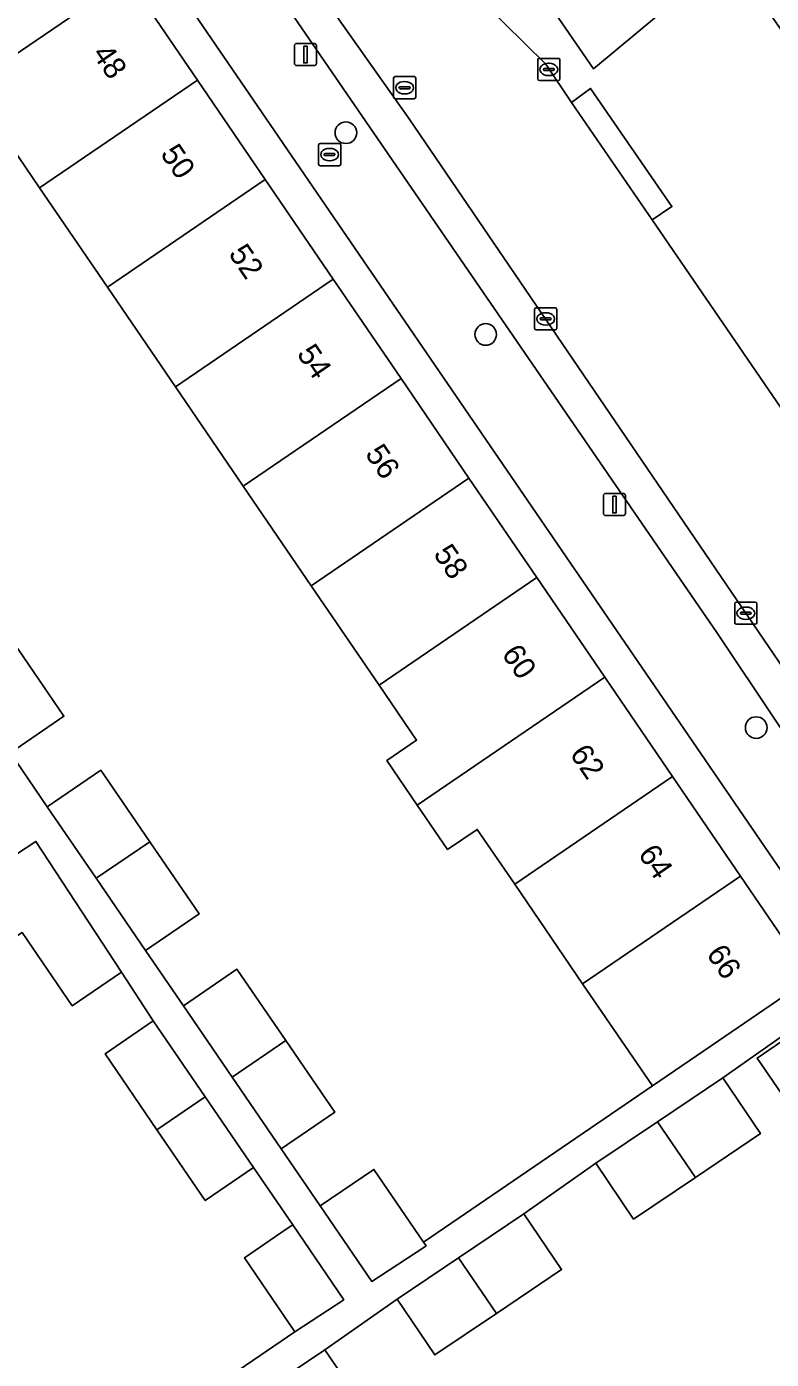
# Model space of a CAD drawing. Extents: x 157445 to 158888, y 383061 to 384688.
# Drawn here: x 158277.7 to 158311.3, y 383793.9 to 383854 of the extents above; entities that cross this region are included whole.
import ezdxf

# ---------------------------------------------------------------- set-up
doc = ezdxf.new("R2010")
doc.units = 0
for name, color, linetype in [('IMGEO_Boom', 7, 'Continuous'), ('IMGEO_Brandkraan', 7, 'Continuous'), ('IMGEO_Erf', 7, 'Continuous'), ('IMGEO_Groenvoorziening', 7, 'Continuous'), ('IMGEO_Kolk', 7, 'Continuous'), ('IMGEO_Lichtmast', 7, 'Continuous'), ('IMGEO_Pand', 7, 'Continuous'), ('IMGEO_Pand_nummerreeks', 7, 'Continuous'), ('IMGEO_Parkeervlak_open', 7, 'Continuous'), ('IMGEO_Rijbaan_lokaal_open', 7, 'Continuous'), ('IMGEO_Rioolput', 7, 'Continuous'), ('IMGEO_Voetpad_open', 7, 'Continuous')]:
    doc.layers.add(name, color=color, linetype=linetype)

msp = doc.modelspace()

# ---------------------------------------------------------------- linework, layer by layer
at = {"layer": 'IMGEO_Boom'}
for centre in [(158292.104, 383849.215), (158298.409, 383840.119), (158310.608, 383822.389)]:
    msp.add_circle(centre, 0.489, dxfattribs=at)
at = {"layer": 'IMGEO_Brandkraan'}
for p, q in [((158290.871, 383847.802), (158290.871, 383848.654)), ((158290.946, 383848.728), (158291.798, 383848.728)), ((158291.872, 383848.654), (158291.872, 383847.802)), ((158291.13, 383848.222), (158291.13, 383848.234)), ((158291.568, 383848.185), (158291.17, 383848.185)), ((158291.173, 383848.271), (158291.571, 383848.271)), ((158291.359, 383848.508), (158291.384, 383848.508)), ((158291.614, 383848.234), (158291.614, 383848.222)), ((158291.798, 383847.728), (158290.946, 383847.728)), ((158291.382, 383847.948), (158291.357, 383847.948))]:
    msp.add_line(p, q, dxfattribs=at)
for points in [[(158290.871, 383847.802), (158290.871, 383848.654)], [(158290.946, 383848.728), (158291.798, 383848.728)], [(158291.872, 383848.654), (158291.872, 383847.802)], [(158291.798, 383847.728), (158290.946, 383847.728)]]:
    msp.add_lwpolyline(points, dxfattribs=at)
for centre, radius, start, end in [((158290.948, 383848.652), 0.0765, 91.55205, 178.44795), ((158290.948, 383848.652), 0.0765, 91.55205, 178.44795), ((158291.796, 383848.652), 0.0765, 1.55205, 88.44795), ((158291.796, 383848.652), 0.0765, 1.55205, 88.44795), ((158291.17, 383848.231), 0.0403, 85.87752, 175.75265), ((158291.167, 383848.221), 0.0366, 178.93798, 274.71019), ((158291.571, 383848.228), 0.043, 264.86636, 352.45326), ((158291.575, 383848.233), 0.0386, 1.73085, 96.63898), ((158290.948, 383847.804), 0.0765, 181.55205, 268.44795), ((158290.948, 383847.804), 0.0765, 181.55205, 268.44795), ((158291.796, 383847.804), 0.0765, 271.55205, 358.44795), ((158291.796, 383847.804), 0.0765, 271.55205, 358.44795)]:
    msp.add_arc(centre, radius, start, end, dxfattribs=at)
for centre, major_axis, ratio, start_param, end_param in [((158291.358, 383848.228), (-0.387, 0.002), 0.722429, 4.712389, 7.853982), ((158291.383, 383848.228), (-0.39, 0.002), 0.717154, 1.570796, 4.712389)]:
    msp.add_ellipse(centre, major_axis=major_axis, ratio=ratio, start_param=start_param, end_param=end_param, dxfattribs=at)
at = {"layer": 'IMGEO_Erf'}
msp.add_lwpolyline([(158283.568, 383857.085), (158282.267, 383856.195), (158285.41, 383851.588), (158288.472, 383847.102), (158291.533, 383842.616), (158294.594, 383838.13), (158297.655, 383833.643), (158300.716, 383829.158), (158303.777, 383824.672), (158306.839, 383820.185), (158309.9, 383815.699), (158313.044, 383811.091), (158314.406, 383812.02)], close=True, dxfattribs=at)
for points in [[(158277.126, 383826.21), (158279.388, 383822.904), (158276.975, 383821.258), (158278.641, 383818.821), (158281.055, 383820.468), (158283.261, 383817.243), (158285.489, 383813.986), (158283.075, 383812.338), (158284.78, 383809.846), (158287.194, 383811.494), (158289.392, 383808.28), (158291.605, 383805.047), (158289.189, 383803.398), (158290.95, 383800.823), (158293.366, 383802.472), (158295.609, 383799.193), (158305.927, 383806.234), (158302.783, 383810.842), (158299.721, 383815.328), (158298.032, 383817.803), (158296.69, 383816.887), (158295.318, 383818.898), (158293.948, 383820.905), (158295.291, 383821.821), (158293.599, 383824.3), (158290.538, 383828.786), (158287.476, 383833.273), (158284.416, 383837.758), (158281.354, 383842.245), (158278.293, 383846.731), (158275.149, 383851.338)], [(158279.716, 383788.261), (158289.804, 383795.148), (158287.528, 383798.479), (158289.419, 383799.768), (158289.706, 383799.964), (158287.94, 383802.549), (158285.762, 383801.064), (158283.578, 383804.261), (158281.243, 383807.679), (158283.42, 383809.165), (158281.992, 383811.358), (158279.766, 383809.84), (158277.501, 383813.155), (158274.827, 383811.404), (158273.238, 383813.832), (158255.342, 383801.626), (158269.302, 383781.158)], [(158315.08, 383810.811), (158309.102, 383806.604), (158310.801, 383804.085), (158307.874, 383802.11), (158305.082, 383800.227), (158303.383, 383802.745), (158300.131, 383800.471), (158301.83, 383797.952), (158298.903, 383795.977), (158296.11, 383794.103), (158294.416, 383796.615), (158291.161, 383794.338), (158292.818, 383791.882)], [(158313.008, 383804.037), (158310.648, 383807.489), (158315.198, 383810.6)]]:
    msp.add_lwpolyline(points, dxfattribs=at)
at = {"layer": 'IMGEO_Groenvoorziening'}
msp.add_lwpolyline([(158307.272, 383855.424), (158304.118, 383860.123), (158300.278, 383856.452), (158303.269, 383852.101)], close=True, dxfattribs=at)
at = {"layer": 'IMGEO_Kolk'}
for p, q in [((158300.755, 383851.642), (158300.755, 383852.494)), ((158300.83, 383852.568), (158301.682, 383852.568)), ((158301.243, 383852.348), (158301.268, 383852.348)), ((158301.756, 383852.494), (158301.756, 383851.642)), ((158301.014, 383852.062), (158301.014, 383852.074)), ((158301.452, 383852.025), (158301.054, 383852.025)), ((158301.057, 383852.111), (158301.455, 383852.111)), ((158301.266, 383851.788), (158301.241, 383851.788)), ((158301.498, 383852.074), (158301.498, 383852.062)), ((158301.682, 383851.568), (158300.83, 383851.568)), ((158300.614, 383840.394), (158300.614, 383841.246)), ((158300.689, 383841.32), (158301.541, 383841.32)), ((158300.873, 383840.814), (158300.873, 383840.826)), ((158301.311, 383840.777), (158300.913, 383840.777)), ((158300.916, 383840.863), (158301.314, 383840.863)), ((158301.102, 383841.1), (158301.127, 383841.1)), ((158301.357, 383840.826), (158301.357, 383840.814)), ((158301.615, 383841.246), (158301.615, 383840.394)), ((158301.541, 383840.32), (158300.689, 383840.32)), ((158301.125, 383840.54), (158301.1, 383840.54)), ((158309.64, 383827.122), (158309.64, 383827.974)), ((158309.715, 383828.048), (158310.567, 383828.048)), ((158309.942, 383827.591), (158310.34, 383827.591)), ((158310.128, 383827.828), (158310.153, 383827.828)), ((158310.641, 383827.974), (158310.641, 383827.122)), ((158310.567, 383827.048), (158309.715, 383827.048)), ((158309.899, 383827.542), (158309.899, 383827.554)), ((158310.337, 383827.505), (158309.939, 383827.505)), ((158310.151, 383827.268), (158310.126, 383827.268)), ((158310.383, 383827.554), (158310.383, 383827.542))]:
    msp.add_line(p, q, dxfattribs=at)
for points in [[(158300.755, 383851.642), (158300.755, 383852.494)], [(158300.83, 383852.568), (158301.682, 383852.568)], [(158301.756, 383852.494), (158301.756, 383851.642)], [(158301.682, 383851.568), (158300.83, 383851.568)], [(158300.614, 383840.394), (158300.614, 383841.246)], [(158300.689, 383841.32), (158301.541, 383841.32)], [(158301.615, 383841.246), (158301.615, 383840.394)], [(158301.541, 383840.32), (158300.689, 383840.32)], [(158309.64, 383827.122), (158309.64, 383827.974)], [(158309.715, 383828.048), (158310.567, 383828.048)], [(158310.641, 383827.974), (158310.641, 383827.122)], [(158310.567, 383827.048), (158309.715, 383827.048)]]:
    msp.add_lwpolyline(points, dxfattribs=at)
for centre, radius, start, end in [((158300.832, 383852.492), 0.0765, 91.55205, 178.44795), ((158300.832, 383852.492), 0.0765, 91.55205, 178.44795), ((158301.68, 383852.492), 0.0765, 1.55205, 88.44795), ((158301.68, 383852.492), 0.0765, 1.55205, 88.44795), ((158300.832, 383851.644), 0.0765, 181.55205, 268.44795), ((158300.832, 383851.644), 0.0765, 181.55205, 268.44795), ((158301.054, 383852.071), 0.0403, 85.87752, 175.75265), ((158301.051, 383852.061), 0.0366, 178.93798, 274.71019), ((158301.455, 383852.068), 0.043, 264.86636, 352.45326), ((158301.459, 383852.073), 0.0386, 1.73085, 96.63898), ((158301.68, 383851.644), 0.0765, 271.55205, 358.44795), ((158301.68, 383851.644), 0.0765, 271.55205, 358.44795), ((158300.691, 383841.244), 0.0765, 91.55205, 178.44795), ((158300.691, 383841.244), 0.0765, 91.55205, 178.44795), ((158300.913, 383840.823), 0.0403, 85.87752, 175.75265), ((158300.91, 383840.813), 0.0366, 178.93798, 274.71019), ((158301.314, 383840.82), 0.043, 264.86636, 352.45326), ((158301.318, 383840.825), 0.0386, 1.73085, 96.63898), ((158301.539, 383841.244), 0.0765, 1.55205, 88.44795), ((158301.539, 383841.244), 0.0765, 1.55205, 88.44795), ((158300.691, 383840.396), 0.0765, 181.55205, 268.44795), ((158300.691, 383840.396), 0.0765, 181.55205, 268.44795), ((158301.539, 383840.396), 0.0765, 271.55205, 358.44795), ((158301.539, 383840.396), 0.0765, 271.55205, 358.44795), ((158309.717, 383827.972), 0.0765, 91.55205, 178.44795), ((158309.717, 383827.972), 0.0765, 91.55205, 178.44795), ((158309.939, 383827.551), 0.0403, 85.87752, 175.75265), ((158310.344, 383827.553), 0.0386, 1.73085, 96.63898), ((158310.565, 383827.972), 0.0765, 1.55205, 88.44795), ((158310.565, 383827.972), 0.0765, 1.55205, 88.44795), ((158309.717, 383827.124), 0.0765, 181.55205, 268.44795), ((158309.717, 383827.124), 0.0765, 181.55205, 268.44795), ((158309.936, 383827.541), 0.0366, 178.93798, 274.71019), ((158310.34, 383827.548), 0.043, 264.86636, 352.45326), ((158310.565, 383827.124), 0.0765, 271.55205, 358.44795), ((158310.565, 383827.124), 0.0765, 271.55205, 358.44795)]:
    msp.add_arc(centre, radius, start, end, dxfattribs=at)
for centre, major_axis, ratio, start_param, end_param in [((158301.242, 383852.068), (-0.387, 0.002), 0.722429, 4.712389, 7.853982), ((158301.267, 383852.068), (-0.39, 0.002), 0.717154, 1.570796, 4.712389), ((158301.101, 383840.82), (-0.387, 0.002), 0.722429, 4.712389, 7.853982), ((158301.126, 383840.82), (-0.39, 0.002), 0.717154, 1.570796, 4.712389), ((158310.127, 383827.548), (-0.387, 0.002), 0.722429, 4.712389, 7.853982), ((158310.152, 383827.548), (-0.39, 0.002), 0.717154, 1.570796, 4.712389)]:
    msp.add_ellipse(centre, major_axis=major_axis, ratio=ratio, start_param=start_param, end_param=end_param, dxfattribs=at)
at = {"layer": 'IMGEO_Lichtmast'}
for p, q in [((158289.783, 383852.34), (158289.783, 383853.14)), ((158289.783, 383853.14), (158289.783, 383852.34)), ((158289.883, 383853.24), (158290.673, 383853.24)), ((158290.673, 383853.24), (158289.883, 383853.24)), ((158290.773, 383853.14), (158290.773, 383852.34)), ((158290.773, 383852.34), (158290.773, 383853.14)), ((158290.673, 383852.24), (158289.883, 383852.24)), ((158289.883, 383852.24), (158290.673, 383852.24)), ((158303.718, 383832.049), (158303.718, 383832.849)), ((158303.718, 383832.849), (158303.718, 383832.049)), ((158303.818, 383832.949), (158304.608, 383832.949)), ((158304.608, 383832.949), (158303.818, 383832.949)), ((158304.708, 383832.849), (158304.708, 383832.049)), ((158304.708, 383832.049), (158304.708, 383832.849)), ((158304.608, 383831.949), (158303.818, 383831.949)), ((158303.818, 383831.949), (158304.608, 383831.949))]:
    msp.add_line(p, q, dxfattribs=at)
for points in [[(158290.203, 383853.115), (158290.353, 383853.115), (158290.353, 383852.365), (158290.203, 383852.365), (158290.203, 383853.115)], [(158304.138, 383832.824), (158304.288, 383832.824), (158304.288, 383832.074), (158304.138, 383832.074), (158304.138, 383832.824)]]:
    msp.add_lwpolyline(points, dxfattribs=at)
for centre, start, end in [((158289.883, 383853.14), 90, 180), ((158289.883, 383853.14), 90, 180), ((158290.673, 383853.14), 0, 90), ((158290.673, 383853.14), 360, 90), ((158289.883, 383852.34), 180, 270), ((158289.883, 383852.34), 180, 270), ((158290.673, 383852.34), 270, 0), ((158290.673, 383852.34), 270, 0), ((158303.818, 383832.849), 90, 180), ((158303.818, 383832.849), 90, 180), ((158304.608, 383832.849), 0, 90), ((158304.608, 383832.849), 360, 90), ((158303.818, 383832.049), 180, 270), ((158303.818, 383832.049), 180, 270), ((158304.608, 383832.049), 270, 0), ((158304.608, 383832.049), 270, 0)]:
    msp.add_arc(centre, 0.1, start, end, dxfattribs=at)
at = {"layer": 'IMGEO_Pand'}
for points in [[(158278.293, 383846.731), (158285.41, 383851.588), (158282.267, 383856.195), (158278.137, 383853.377), (158275.149, 383851.338)], [(158278.293, 383846.731), (158281.354, 383842.245), (158288.472, 383847.102), (158285.41, 383851.588)], [(158284.416, 383837.758), (158291.533, 383842.616), (158288.472, 383847.102), (158281.354, 383842.245)], [(158284.416, 383837.758), (158287.476, 383833.273), (158294.594, 383838.13), (158291.533, 383842.616)], [(158297.655, 383833.643), (158294.594, 383838.13), (158287.476, 383833.273), (158290.538, 383828.786)], [(158297.655, 383833.643), (158290.538, 383828.786), (158293.599, 383824.3), (158300.716, 383829.158)], [(158300.716, 383829.158), (158293.599, 383824.3), (158295.291, 383821.821), (158293.948, 383820.905), (158295.318, 383818.898), (158303.777, 383824.672)], [(158277.126, 383826.21), (158274.713, 383824.564), (158276.975, 383821.258), (158279.388, 383822.904)], [(158299.721, 383815.328), (158306.839, 383820.185), (158303.777, 383824.672), (158295.318, 383818.898), (158296.69, 383816.887), (158298.032, 383817.803)], [(158278.641, 383818.821), (158280.847, 383815.596), (158283.261, 383817.243), (158281.055, 383820.468)], [(158309.9, 383815.699), (158306.839, 383820.185), (158299.721, 383815.328), (158302.783, 383810.842)], [(158273.136, 383813.988), (158273.238, 383813.832), (158274.827, 383811.404), (158277.501, 383813.155), (158279.766, 383809.84), (158281.992, 383811.358), (158278.13, 383817.257)], [(158283.261, 383817.243), (158280.847, 383815.596), (158283.075, 383812.338), (158285.489, 383813.986)], [(158309.9, 383815.699), (158302.783, 383810.842), (158305.927, 383806.234), (158308.915, 383808.273), (158313.044, 383811.091)], [(158284.78, 383809.846), (158286.977, 383806.632), (158289.392, 383808.28), (158287.194, 383811.494)], [(158315.198, 383810.6), (158310.648, 383807.489), (158313.008, 383804.037), (158314.923, 383801.236), (158316.102, 383802.042), (158319.462, 383804.339)], [(158283.42, 383809.165), (158281.243, 383807.679), (158283.578, 383804.261), (158285.755, 383805.746)], [(158289.392, 383808.28), (158286.977, 383806.632), (158289.189, 383803.398), (158291.605, 383805.047)], [(158306.16, 383804.618), (158307.874, 383802.11), (158310.801, 383804.085), (158309.102, 383806.604)], [(158287.94, 383802.549), (158285.755, 383805.746), (158283.578, 383804.261), (158285.762, 383801.064)], [(158307.874, 383802.11), (158306.16, 383804.618), (158303.383, 383802.745), (158305.082, 383800.227)], [(158290.95, 383800.823), (158293.277, 383797.422), (158295.659, 383798.983), (158295.723, 383799.027), (158295.609, 383799.193), (158293.366, 383802.472)], [(158289.706, 383799.964), (158289.419, 383799.768), (158287.528, 383798.479), (158289.804, 383795.148), (158292.009, 383796.592)], [(158297.189, 383798.485), (158298.903, 383795.977), (158301.83, 383797.952), (158300.131, 383800.471)], [(158298.903, 383795.977), (158297.189, 383798.485), (158294.416, 383796.615), (158296.11, 383794.103)], [(158291.161, 383794.338), (158288.217, 383792.351), (158289.888, 383789.906), (158292.818, 383791.882)]]:
    msp.add_lwpolyline(points, close=True, dxfattribs=at)
at = {"layer": 'IMGEO_Parkeervlak_open'}
for points in [[(158317.136, 383817.278), (158294.957, 383849.841), (158290.926, 383855.558), (158266.381, 383891.427), (158256.656, 383905.574)], [(158256.861, 383902.472), (158283.979, 383862.899), (158286.012, 383859.903), (158308.868, 383826.633), (158314.179, 383818.673), (158314.799, 383818.227), (158315.648, 383818.052)]]:
    msp.add_lwpolyline(points, dxfattribs=at)
at = {"layer": 'IMGEO_Rijbaan_lokaal_open'}
msp.add_lwpolyline([(158315.651, 383831.074), (158305.913, 383845.281), (158302.281, 383850.584), (158301.122, 383852.309), (158299.238, 383854.158), (158295.004, 383858.427), (158293.208, 383861.205), (158290.787, 383864.545), (158270.586, 383893.988), (158270.461, 383894.175), (158266.381, 383891.427), (158290.926, 383855.558), (158294.957, 383849.841), (158317.136, 383817.278), (158318.12, 383815.849)], dxfattribs=at)
at = {"layer": 'IMGEO_Rioolput'}
for p, q in [((158294.256, 383850.817), (158294.256, 383851.669)), ((158294.331, 383851.743), (158295.183, 383851.743)), ((158295.257, 383851.669), (158295.257, 383850.817)), ((158294.515, 383851.237), (158294.515, 383851.249)), ((158294.953, 383851.2), (158294.555, 383851.2)), ((158294.558, 383851.286), (158294.956, 383851.286)), ((158294.744, 383851.523), (158294.769, 383851.523)), ((158294.999, 383851.249), (158294.999, 383851.237)), ((158295.183, 383850.743), (158294.331, 383850.743)), ((158294.767, 383850.963), (158294.742, 383850.963))]:
    msp.add_line(p, q, dxfattribs=at)
for points in [[(158294.256, 383850.817), (158294.256, 383851.669)], [(158294.331, 383851.743), (158295.183, 383851.743)], [(158295.257, 383851.669), (158295.257, 383850.817)], [(158295.183, 383850.743), (158294.331, 383850.743)]]:
    msp.add_lwpolyline(points, dxfattribs=at)
for centre, radius, start, end in [((158294.333, 383851.667), 0.0765, 91.55205, 178.44795), ((158294.333, 383851.667), 0.0765, 91.55205, 178.44795), ((158295.181, 383851.667), 0.0765, 1.55205, 88.44795), ((158295.181, 383851.667), 0.0765, 1.55205, 88.44795), ((158294.555, 383851.246), 0.0403, 85.87752, 175.75265), ((158294.552, 383851.236), 0.0366, 178.93798, 274.71019), ((158294.956, 383851.243), 0.043, 264.86636, 352.45326), ((158294.96, 383851.248), 0.0386, 1.73085, 96.63898), ((158294.333, 383850.819), 0.0765, 181.55205, 268.44795), ((158294.333, 383850.819), 0.0765, 181.55205, 268.44795), ((158295.181, 383850.819), 0.0765, 271.55205, 358.44795), ((158295.181, 383850.819), 0.0765, 271.55205, 358.44795)]:
    msp.add_arc(centre, radius, start, end, dxfattribs=at)
for centre, major_axis, ratio, start_param, end_param in [((158294.743, 383851.243), (-0.387, 0.002), 0.722429, 4.712389, 7.853982), ((158294.768, 383851.243), (-0.39, 0.002), 0.717154, 1.570796, 4.712389)]:
    msp.add_ellipse(centre, major_axis=major_axis, ratio=ratio, start_param=start_param, end_param=end_param, dxfattribs=at)
at = {"layer": 'IMGEO_Voetpad_open'}
for points in [[(158252.755, 383908.194), (158250.603, 383905.26), (158282.821, 383858.177), (158283.568, 383857.085), (158314.406, 383812.02), (158315.08, 383810.811), (158315.198, 383810.6), (158319.462, 383804.339), (158323.13, 383799.314), (158327.979, 383792.222), (158330.843, 383787.992), (158333.261, 383790.767)], [(158321.054, 383850.357), (158319.674, 383851.933), (158318.294, 383853.51), (158317.961, 383853.89), (158314.033, 383850.522), (158309.45, 383857.17), (158308.876, 383857.993), (158306.048, 383862.049), (158303.839, 383865.375), (158301.823, 383863.44), (158301.383, 383863.021), (158297.986, 383859.788), (158295.004, 383858.427), (158299.238, 383854.158), (158301.122, 383852.309), (158302.281, 383850.584), (158303.14, 383851.213), (158306.807, 383845.887), (158305.913, 383845.281), (158315.651, 383831.074)], [(158315.648, 383818.052), (158314.799, 383818.227), (158314.179, 383818.673), (158308.868, 383826.633), (158286.012, 383859.903)], [(158275.149, 383851.338), (158278.137, 383853.377), (158282.267, 383856.195)], [(158313.044, 383811.091), (158308.915, 383808.273), (158305.927, 383806.234), (158295.609, 383799.193), (158295.723, 383799.027), (158295.659, 383798.983), (158293.277, 383797.422), (158290.95, 383800.823), (158289.189, 383803.398), (158286.977, 383806.632), (158284.78, 383809.846), (158283.075, 383812.338), (158280.847, 383815.596), (158278.641, 383818.821), (158276.975, 383821.258)], [(158273.136, 383813.988), (158278.13, 383817.257), (158281.992, 383811.358), (158283.42, 383809.165), (158285.755, 383805.746), (158287.94, 383802.549), (158289.706, 383799.964), (158292.009, 383796.592), (158289.804, 383795.148), (158279.716, 383788.261)], [(158288.217, 383792.351), (158291.161, 383794.338), (158294.416, 383796.615), (158297.189, 383798.485), (158300.131, 383800.471), (158303.383, 383802.745), (158306.16, 383804.618), (158309.102, 383806.604), (158315.08, 383810.811)]]:
    msp.add_lwpolyline(points, dxfattribs=at)
for points in [[(158307.272, 383855.424), (158303.269, 383852.101), (158300.278, 383856.452), (158304.118, 383860.123)], [(158305.913, 383845.281), (158306.807, 383845.887), (158303.14, 383851.213), (158302.281, 383850.584)]]:
    msp.add_lwpolyline(points, close=True, dxfattribs=at)

# ---------------------------------------------------------------- texts
at = {"layer": 'IMGEO_Pand_nummerreeks'}
for s, p in [('48', (158280.632, 383852.771)), ('50', (158283.71, 383848.261)), ('52', (158286.785, 383843.755)), ('54', (158289.863, 383839.242)), ('56', (158292.941, 383834.732)), ('58', (158296.021, 383830.219)), ('60', (158299.099, 383825.709)), ('62', (158302.173, 383821.203)), ('64', (158305.252, 383816.69)), ('66', (158308.33, 383812.18))]:
    msp.add_text(s, height=1, rotation=304.30792, dxfattribs=at).set_placement(p)

doc.saveas('drawing.dxf')
